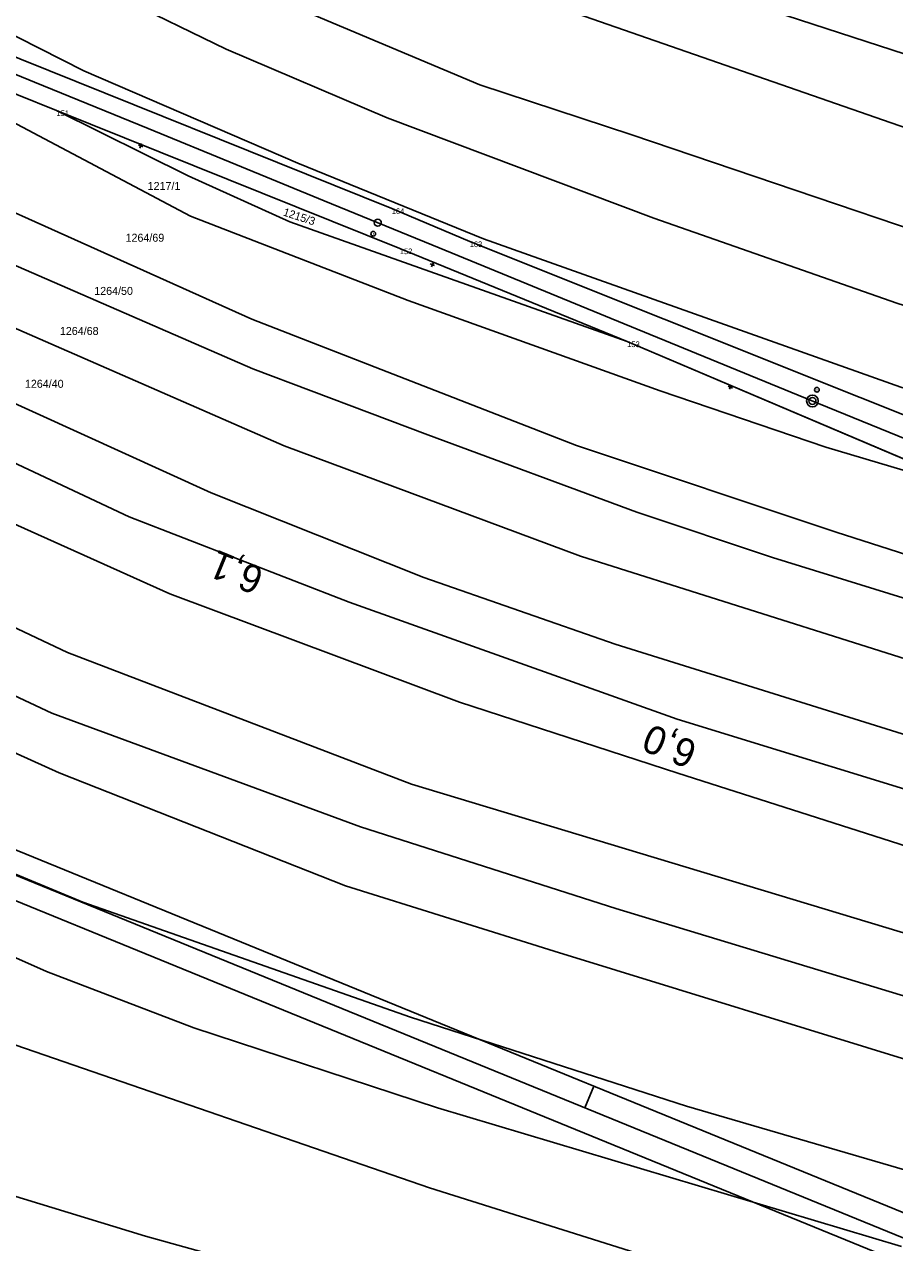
# Model space of a CAD drawing. Extents: x -779330 to -774454, y -1144748 to -1142831.
# Drawn here: x -776332 to -776147.1, y -1144378.3 to -1144119.5 of the extents above; entities that cross this region are included whole.
import ezdxf

# ---------------------------------------------------------------- set-up
doc = ezdxf.new("R2010")
doc.units = 0
for name, color, linetype in [('Hranice parcel', 7, 'Continuous'), ('Parcelní čísla', 7, 'Continuous'), ('SŽDC', 7, 'Continuous'), ('Vrstva 1', 7, 'Continuous'), ('Vrstva 53', 7, 'Continuous'), ('Vrstva 60', 7, 'Continuous'), ('Vrstva 7', 7, 'Continuous')]:
    doc.layers.add(name, color=color, linetype=linetype)

msp = doc.modelspace()

# ---------------------------------------------------------------- linework, layer by layer
at = {"layer": 'Hranice parcel'}
msp.add_line((-776203.96, -1144186.83), (-776126.28, -1144219.86), dxfattribs=at)
for points in [[(-776600.02, -1143957.46), (-776528.66, -1143976.76), (-776457.94, -1143997.05), (-776442.28, -1144001.65), (-776398.64, -1144017.46), (-776351.09, -1144039.08), (-776262.34, -1144082.22), (-776198.07, -1144108.44), (-776142.1, -1144126.74), (-776090.77, -1144146.14)], [(-776599.74, -1143971.88), (-776539.25, -1143987.71), (-776480.91, -1144004.77), (-776433.76, -1144019.99), (-776387.97, -1144037.81), (-776365.6, -1144047.46), (-776310.35, -1144075.44), (-776280.61, -1144089.36), (-776258.25, -1144098.68), (-776214.75, -1144117.12), (-776097.7, -1144157.79)], [(-776601.27, -1143990.4), (-776527.05, -1144013.4), (-776476.25, -1144029.92), (-776451.83, -1144038), (-776413.3, -1144052.52), (-776382.54, -1144065.64), (-776348.92, -1144080.63), (-776308.77, -1144099.81), (-776271.78, -1144116.96), (-776235.24, -1144132.31), (-776202.98, -1144142.91), (-776103.02, -1144176.77)], [(-776603.25, -1144004.14), (-776531.61, -1144026.86), (-776500.12, -1144036.38), (-776435.33, -1144057.94), (-776392.95, -1144075.37), (-776356.59, -1144091.91), (-776289.18, -1144124.7), (-776254.94, -1144139.28), (-776198.32, -1144160.66), (-776146.7, -1144178.71), (-776104.57, -1144192.02)], [(-776113.15, -1144215.23), (-776237.42, -1144165.58), (-776253.98, -1144158.55), (-776339.24, -1144124.31), (-776431.42, -1144085.55), (-776524.5, -1144047.63), (-776566.07, -1144030.95)], [(-776104.82, -1144208.77), (-776145.81, -1144196.56), (-776234.45, -1144165.02), (-776273.96, -1144148.97), (-776319.4, -1144129.31), (-776389.63, -1144093.66), (-776429.56, -1144076.12), (-776519.73, -1144046.81), (-776566.07, -1144030.95)], [(-776606.26, -1144039.66), (-776542.86, -1144059.4), (-776473.03, -1144080.58), (-776435.07, -1144094.71), (-776377.12, -1144119.5), (-776337.3, -1144138.78), (-776296.76, -1144160.19), (-776250.47, -1144178.1), (-776196.94, -1144197.35), (-776161.72, -1144209.31), (-776126.28, -1144219.86)], [(-776527.2, -1144055.02), (-776434.38, -1144092.81), (-776342.13, -1144130.92), (-776325.22, -1144137.73)], [(-776110.54, -1144243.08), (-776159.55, -1144227.35), (-776214.73, -1144208.93), (-776283.73, -1144182.09), (-776414.91, -1144123.19), (-776432.86, -1144115.28), (-776478.51, -1144099.13), (-776510.43, -1144089.03), (-776541.53, -1144079.23), (-776582.13, -1144067.05), (-776608.45, -1144059.24)], [(-776609.22, -1144072.59), (-776549.62, -1144089.18), (-776477.02, -1144111.9), (-776421.35, -1144132.65), (-776283.48, -1144192.64), (-776246.29, -1144206.67), (-776201.94, -1144223.07), (-776173.05, -1144232.7), (-776113.8, -1144251.1)], [(-776118.46, -1144262.59), (-776213.85, -1144232.45), (-776276.83, -1144209.03), (-776421.73, -1144145.66), (-776463.81, -1144128.69), (-776555.71, -1144099.28), (-776609.79, -1144083.15)], [(-776610.76, -1144099.41), (-776538.78, -1144121.66), (-776471.83, -1144143.05), (-776416.15, -1144164.19), (-776357.31, -1144189.49), (-776292.36, -1144218.98), (-776247.15, -1144237), (-776206.49, -1144251.17), (-776124.24, -1144276.84)], [(-776611.4, -1144111.19), (-776509.83, -1144141.71), (-776435.48, -1144167.03), (-776362.11, -1144199.54), (-776309.74, -1144224.06), (-776263.02, -1144242.23), (-776193.31, -1144267.08), (-776128.39, -1144287.08)], [(-776132.3, -1144298.01), (-776193.18, -1144278.57), (-776239.59, -1144263.48), (-776301.12, -1144240.48), (-776347.51, -1144219.6), (-776446.62, -1144176.16), (-776482.94, -1144162.91), (-776612.01, -1144123.26)], [(-776325.22, -1144137.73), (-776252.27, -1144167.08), (-776203.96, -1144186.83)], [(-776325.22, -1144137.73), (-776297.26, -1144151.64), (-776275.64, -1144161.42), (-776203.96, -1144186.83)], [(-776145.67, -1144379.15), (-776244.27, -1144349.66), (-776296.05, -1144332.67), (-776327.31, -1144320.71), (-776369.01, -1144302.14), (-776451.08, -1144263.13), (-776474.26, -1144253.76), (-776497.45, -1144244.88), (-776532.83, -1144233.01), (-776621.67, -1144207.38)], [(-776387.71, -1144222.25), (-776322.84, -1144252.89), (-776249.8, -1144280.91), (-776136.12, -1144315.24)], [(-776148.27, -1144396.56), (-776184.13, -1144386.14), (-776245.97, -1144366.65), (-776333.82, -1144336.34), (-776380.08, -1144316.22), (-776443.83, -1144284.45), (-776499.21, -1144261.37), (-776533.49, -1144250.6), (-776623.75, -1144225.26)], [(-776392.74, -1144234.57), (-776326.16, -1144265.8), (-776260.62, -1144289.93), (-776206.39, -1144307.32), (-776138.04, -1144328.07)], [(-776139.95, -1144340.89), (-776219.46, -1144316.38), (-776263.77, -1144302.5), (-776324.6, -1144278.51), (-776377.44, -1144254.65), (-776396.98, -1144244.94)], [(-776143.31, -1144363.37), (-776191.33, -1144349.34), (-776249.99, -1144330.39), (-776319.63, -1144305.99), (-776364.66, -1144287.25), (-776444.24, -1144249.74)], [(-776631.25, -1144276.64), (-776433.42, -1144338.06), (-776306.29, -1144376.93), (-776251.08, -1144392.3), (-776152.53, -1144423.14)]]:
    msp.add_lwpolyline(points, dxfattribs=at)
at = {"layer": 'SŽDC'}
msp.add_lwpolyline([(-776342.13, -1144130.92), (-776325.22, -1144137.73), (-776252.27, -1144167.08), (-776203.96, -1144186.83), (-776126.28, -1144219.86), (-776116.08, -1144223.44), (-776104.51, -1144228.21), (-776098.59, -1144230.98), (-776096.98, -1144226.78), (-776095.57, -1144223.11), (-776096.42, -1144222.78), (-776101.21, -1144220.07), (-776105.05, -1144218.51), (-776109.59, -1144216.67), (-776113.15, -1144215.23), (-776237.42, -1144165.58), (-776253.98, -1144158.55), (-776339.24, -1144124.31)], dxfattribs=at)
at = {"layer": 'Vrstva 1'}
msp.add_line((-776211.04, -1144345.06), (-776212.93, -1144349.68), dxfattribs=at)
for points in [[(-775713.68, -1144238.31), (-776879.99, -1143761.57), (-776992.36, -1144036.48), (-775826.05, -1144513.22)], [(-775828.78, -1144506.7), (-776985.84, -1144033.74), (-776877.25, -1143768.09), (-775720.2, -1144241.05)], [(-775726.71, -1144243.78), (-776684.76, -1143852.17), (-776789.57, -1144108.58), (-775831.52, -1144500.19)], [(-775831.52, -1144500.19), (-776789.57, -1144108.58), (-776684.76, -1143852.17), (-775726.71, -1144243.78)]]:
    msp.add_lwpolyline(points, close=True, dxfattribs=at)
msp.add_lwpolyline([(-776044.9, -1144248.56), (-776062.23, -1144241.45), (-776078.99, -1144234.58), (-776085.49, -1144231.92), (-776091.15, -1144229.58), (-776100.22, -1144225.86), (-776117.47, -1144218.8), (-776139.19, -1144209.89), (-776163.33, -1144200), (-776180.57, -1144192.93), (-776204.58, -1144183.08), (-776229.27, -1144172.96), (-776243.87, -1144166.96), (-776268.36, -1144156.92), (-776287.1, -1144149.26), (-776305.75, -1144141.61), (-776329.89, -1144131.72), (-776350.5, -1144123.27)], dxfattribs=at)
at = {"layer": 'Vrstva 53'}
msp.add_lwpolyline([(-776339.24, -1144124.31), (-776253.98, -1144158.55), (-776237.42, -1144165.58), (-776113.15, -1144215.23), (-776109.59, -1144216.67), (-776105.05, -1144218.51), (-776101.21, -1144220.07), (-776096.42, -1144222.78), (-776095.57, -1144223.11), (-776096.98, -1144226.78), (-776098.59, -1144230.98), (-776104.51, -1144228.21), (-776116.08, -1144223.44), (-776126.28, -1144219.86), (-776203.96, -1144186.83), (-776252.27, -1144167.08), (-776325.22, -1144137.73), (-776342.13, -1144130.92)], dxfattribs=at)
msp.add_lwpolyline([(-776339.24, -1144124.31), (-776253.98, -1144158.55), (-776237.42, -1144165.58), (-776113.15, -1144215.23), (-776109.59, -1144216.67), (-776105.05, -1144218.51), (-776101.21, -1144220.07), (-776096.42, -1144222.78), (-776095.57, -1144223.11), (-776096.98, -1144226.78), (-776098.59, -1144230.98), (-776104.51, -1144228.21), (-776116.08, -1144223.44), (-776126.28, -1144219.86), (-776203.96, -1144186.83), (-776252.27, -1144167.08), (-776325.22, -1144137.73), (-776342.13, -1144130.92)], dxfattribs=at)
at = {"layer": 'Vrstva 60'}
for p, q in [((-776325.22, -1144137.73), (-776325.22, -1144137.73)), ((-776253.98, -1144158.55), (-776253.98, -1144158.55)), ((-776237.42, -1144165.58), (-776237.42, -1144165.58)), ((-776252.27, -1144167.08), (-776252.27, -1144167.08)), ((-776203.96, -1144186.83), (-776203.96, -1144186.83))]:
    msp.add_line(p, q, dxfattribs=at)
at = {"layer": 'Vrstva 7'}
for p, q in [((-776306.85, -1144145.45), (-776307.77, -1144145.08)), ((-776307.5, -1144145.73), (-776307.12, -1144144.8)), ((-776257.85, -1144163.97), (-776257.95, -1144163.93)), ((-776244.87, -1144170.7), (-776245.79, -1144170.32)), ((-776245.52, -1144170.97), (-776245.14, -1144170.04)), ((-776181.58, -1144196.73), (-776182.5, -1144196.35)), ((-776182.23, -1144197), (-776181.85, -1144196.07)), ((-776163.59, -1144197.12), (-776163.68, -1144197.08))]:
    msp.add_line(p, q, dxfattribs=at)
for centre, radius in [((-776256.95, -1144161.6), 0.75), ((-776257.9, -1144163.95), 0.5), ((-776163.64, -1144197.1), 0.5), ((-776164.6, -1144199.47), 1.25), ((-776164.6, -1144199.47), 0.752)]:
    msp.add_circle(centre, radius, dxfattribs=at)

# ---------------------------------------------------------------- texts
at = {"layer": 'Parcelní čísla'}
for s, p in [('1217/1', (-776305.84, -1144154.64)), ('1264/69', (-776310.53, -1144165.64)), ('1264/50', (-776317.18, -1144176.94)), ('1264/68', (-776324.48, -1144185.45)), ('1264/40', (-776331.91, -1144196.67))]:
    msp.add_text(s, height=1.7, dxfattribs=at).set_placement(p)
msp.add_text('1215/3', height=1.7, rotation=342, dxfattribs=at).set_placement((-776277.19, -1144160.04))
at = {"layer": 'Vrstva 60'}
for s, p in [('151', (-776325.22, -1144138.93)), ('164', (-776253.98, -1144159.75)), ('163', (-776237.42, -1144166.78)), ('152', (-776252.27, -1144168.28)), ('153', (-776203.96, -1144188.03))]:
    msp.add_text(s, height=1.2, dxfattribs=at).set_placement(p)
at = {"layer": 'Vrstva 7'}
for s, rotation, p in [('6,1', 157.6981, (-776280.74, -1144235.26)), ('6,0', 157.7045, (-776188.67, -1144272.2))]:
    msp.add_text(s, height=6, rotation=rotation, dxfattribs=at).set_placement(p)

doc.saveas('drawing.dxf')
